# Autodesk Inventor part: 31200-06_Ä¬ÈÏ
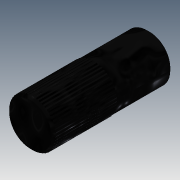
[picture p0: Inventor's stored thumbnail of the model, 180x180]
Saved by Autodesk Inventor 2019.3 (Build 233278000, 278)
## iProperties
Created: 2010-06
Part Number: 31200-06_Ä¬ÈÏ
Material: Ogólny
Document SubType Name: Modeling
Designer: CADENGINEERING4
Density: 1 g/cm^3
Appearance: Czarny
Author: CADENGINEERING4
Revision Number: ÈÎºÎ
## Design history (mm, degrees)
feature "NONE"
node "Bryła1"
